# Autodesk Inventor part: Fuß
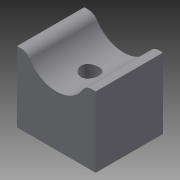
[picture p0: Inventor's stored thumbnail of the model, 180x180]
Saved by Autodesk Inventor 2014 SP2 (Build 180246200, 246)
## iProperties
Created: 2015-04
Part Number: Fuß
Material: Generisch
Document SubType Name: Modeling
Designer: e_krauts
Density: 1 g/cm^3
Appearance: Vorgabe
Mass: 34.0103 g
Surface Area: 76.7953 cm^2
Volume: 34.0103 cm^3
Author: e_krauts
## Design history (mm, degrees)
sketch "Skizze1"
  geometry: L1 (-19, 16.25)-(19, 16.25); L2 (19, 16.25)-(19, -16.25); L3 (19, -16.25)-(-19, -16.25); L4 (-19, -16.25)-(-19, 16.25); L5 (-19, 16.25)-(19, -16.25); L6 (19, 16.25)-(-19, -16.25); 1 further point
  constraints: 12 end point, 2 midpoint, 2 parallel, 1 horizontal, 1 perpendicular
  dimensions: "d0" = 38 distance of L2.end L3.end; "d1" = 32.5 distance of L1.end L2.end
extrude "Extrusion1" new body sketch "Skizze1" distance "d2" = 34; taper "d3" = 0 deg
sketch "Skizze2"
  geometry: L1 (0, 0)-(38, 0) reference; L2 (0, 34)-(38, 34) reference; L3 (0, 0)-(0, 34) reference; L4 (19, 34)-(19, 0); L5 (5.045, 34)-(32.955, 34); A1 r 15 centre (19, 39.5) between (5.045, 34) and (32.955, 34); 1 further point
  constraints: 4 end point, 3 point on line, 2 midpoint, 2 point on circle, 1 centre point, 1 parallel, 1 perpendicular
  dimensions: "d4" = 30 diameter of A1; "d5" = 39.5 distance from line of L1 A1.centre
extrude "Extrusion2" cut sketch "Skizze2" stored distance "d6" = 34; taper "d7" = 0 deg
fillet "Rundung1" dims "d8" = 5
sketch "Skizze3"
  geometry: 2 further points
  constraints: 1 coincident
hole "Bohrung1" sketch "Skizze3" at (0, 0) diameter "d9" = 8.5; stored, may be unused: countersink angle "d13" = 90 deg, drill point angle "d15" = 118 deg; dims "d10" = 6, "d11" = 15, "d12" = 2, "d14" = 8
node "Volumenkörper1"
